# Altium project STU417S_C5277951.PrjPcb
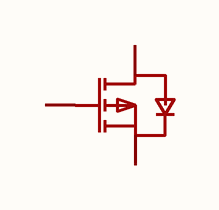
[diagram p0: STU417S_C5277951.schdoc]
1 sheet, 1 parts. Net scope: global (net labels, ports and power ports of the same name join across sheets).

## Sheet STU417S_C5277951.schdoc
size 127 x 101 mm

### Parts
Q?  stu417s  [TO-252-3_L6.5-W5.8-P4.60-LS9.9-BR]  (value not drawn)

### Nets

Not connected (* = marked no-connect by the designer): Q? 1(G) 2(D) 3(S)

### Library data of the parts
Q? = stu417s: 数量:1个P沟道;漏源电压(Vdss):40V;连续漏极电流(Id):50A;导通电阻(RDS(on)):10.5mΩ@10V；14.2mΩ@4.5V;耗散功率(Pd):55W;阈值电压(Vgs(th)):1.6V@250uA;; Manufacturer: MSKSEMI(美森科); Symbol: STU417S_C5277951; AddInBom: yes; ModelId: d90e945a06994ea488a623a0f9e40a94; ModelTransform: 389.763,255.905,0,0,0,0,-25.354,0,0; Number: 1个P沟道; Drain to Source Voltage: 40V; Current - Continuous Drain(Id): 50A; Pd - Power Dissipation: 55W; Gate Charge(Qg): 28nC@10V; Input Capacitance(Ciss): 2.05nF@20V; Reverse Transfer Capacitance (Crss@Vds): 150pF@20V; Type: P沟道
